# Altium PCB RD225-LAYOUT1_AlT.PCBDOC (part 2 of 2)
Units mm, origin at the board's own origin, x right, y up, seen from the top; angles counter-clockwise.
Board outline 85.6 x 53.98 mm, 2 copper layers (TOP, BOTTOM), stack 0 mm thick; 16 components, 11 nets, 48 pads, 0 vias.
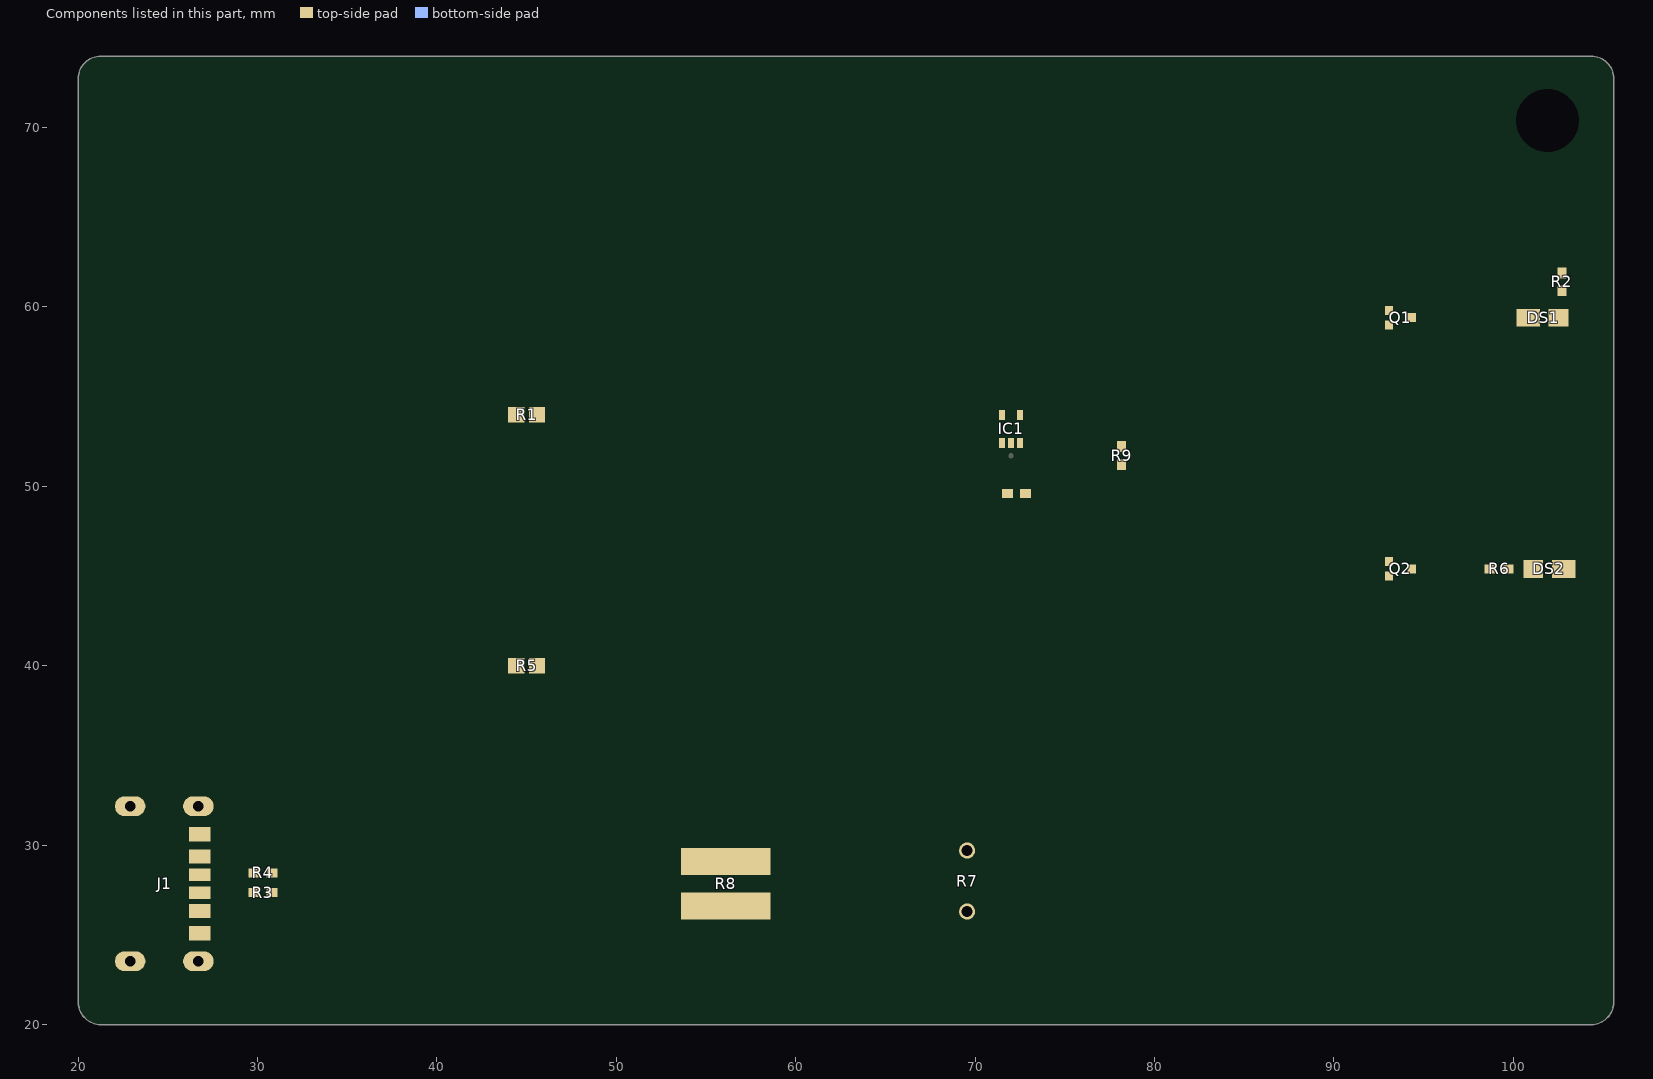
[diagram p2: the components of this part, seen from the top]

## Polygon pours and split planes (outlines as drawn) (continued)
no net on Top Overlay "TOPOVERLAY89" (solid, pour order 0): 25 vertices, not listed, extent 97.533,38.49 99.363,39.797
no net on Top Overlay "TOPOVERLAY88" (solid, pour order 0): 89.168,36.661 89.168,36.922 88.907,36.922 88.907,37.183 89.43,37.183 89.43,36.922 89.691,36.922 89.691,36.661
no net on Top Overlay "TOPOVERLAY87" (solid, pour order 0): 23 vertices, not listed, extent 96.226,34.308 98.056,36.138
no net on Top Overlay "TOPOVERLAY86" (solid, pour order 0): 100.932,35.354 100.932,35.615 101.193,35.615 101.193,35.354
no net on Top Overlay "TOPOVERLAY85" (solid, pour order 0): 99.625,34.569 99.625,34.831 99.886,34.831 99.886,34.569
no net on Top Overlay "TOPOVERLAY84" (solid, pour order 0): 101.193,33.785 101.193,34.046 101.454,34.046 101.454,33.785
no net on Top Overlay "TOPOVERLAY83" (solid, pour order 0): 93.089,30.387 93.089,30.648 93.351,30.648 93.351,31.694 93.612,31.694 93.612,31.432 93.874,31.432 93.874,31.694 94.135,31.694 94.135,31.171 94.396,31.171 94.396,30.91 93.612,30.91 93.612,30.387
no net on Top Overlay "TOPOVERLAY82" (solid, pour order 0): 88.646,39.275 88.646,41.104 90.475,41.104 90.475,39.275
no net on Top Overlay "TOPOVERLAY81" (solid, pour order 0): 97.272,39.013 97.272,39.275 97.533,39.275 97.533,39.013
no net on Top Overlay "TOPOVERLAY80" (solid, pour order 0): 94.919,34.569 94.919,34.831 95.181,34.831 95.181,34.569
no net on Top Overlay "TOPOVERLAY79" (solid, pour order 0): 89.691,37.968 89.691,38.752 89.953,38.752 89.953,38.49 90.737,38.49 90.737,38.229 89.953,38.229 89.953,37.968
no net on Top Overlay "TOPOVERLAY78" (solid, pour order 0): 96.488,29.603 96.488,29.864 96.749,29.864 96.749,29.603
no net on Top Overlay "TOPOVERLAY77" (solid, pour order 0): 100.409,32.739 100.409,33.001 100.67,33.001 100.67,32.739
no net on Top Overlay "TOPOVERLAY76" (solid, pour order 0): 100.147,33.001 100.147,33.262 100.409,33.262 100.409,33.001
no net on Top Overlay "TOPOVERLAY75" (solid, pour order 0): 89.691,32.739 89.691,33.001 89.953,33.001 89.953,33.262 90.475,33.262 90.475,33.001 90.214,33.001 90.214,32.739
no net on Top Overlay "TOPOVERLAY74" (solid, pour order 0): 92.044,31.432 92.044,31.694 91.521,31.694 91.521,31.955 91.782,31.955 91.782,32.217 92.044,32.217 92.044,31.955 92.305,31.955 92.305,31.432
no net on Top Overlay "TOPOVERLAY73" (solid, pour order 0): 33 vertices, not listed, extent 99.102,33.785 101.454,37.183
no net on Top Overlay "TOPOVERLAY72" (solid, pour order 0): 100.67,37.183 100.67,37.445 101.193,37.445 101.193,37.183
no net on Top Overlay "TOPOVERLAY71" (solid, pour order 0): 99.625,36.661 99.625,37.445 99.886,37.445 99.886,36.922 100.147,36.922 100.147,37.183 100.409,37.183 100.409,36.661
no net on Top Overlay "TOPOVERLAY70" (solid, pour order 0): 90.475,33.262 90.475,33.524 90.214,33.524 90.214,33.785 90.737,33.785 90.737,33.262
no net on Top Overlay "TOPOVERLAY69" (solid, pour order 0): 97.011,28.557 97.011,28.818 97.533,28.818 97.533,28.557
no net on Top Overlay "TOPOVERLAY68" (solid, pour order 0): 93.612,29.603 93.612,29.864 93.351,29.864 93.351,30.125 93.612,30.125 93.612,30.387 93.874,30.387 93.874,29.603
no net on Top Overlay "TOPOVERLAY67" (solid, pour order 0): 92.044,30.387 92.044,30.648 92.305,30.648 92.305,30.387
no net on Top Overlay "TOPOVERLAY66" (solid, pour order 0): 99.363,31.432 99.363,31.694 99.625,31.694 99.625,31.432
no net on Top Overlay "TOPOVERLAY65" (solid, pour order 0): 88.646,30.387 88.646,30.648 88.907,30.648 88.907,31.171 89.168,31.171 89.168,30.91 89.691,30.91 89.691,30.648 89.43,30.648 89.43,30.387
no net on Top Overlay "TOPOVERLAY64" (solid, pour order 0): 96.749,39.797 96.749,40.32 97.011,40.32 97.011,39.797
no net on Top Overlay "TOPOVERLAY63" (solid, pour order 0): 94.658,28.296 94.658,28.557 94.396,28.557 94.396,28.818 95.181,28.818 95.181,28.296
no net on Top Overlay "TOPOVERLAY62" (solid, pour order 0): 98.056,32.739 98.056,33.524 98.579,33.524 98.579,33.262 98.318,33.262 98.318,32.739
no net on Top Overlay "TOPOVERLAY61" (solid, pour order 0): 97.795,30.648 97.795,30.91 98.056,30.91 98.056,30.648
no net on Top Overlay "TOPOVERLAY60" (solid, pour order 0): 91.521,30.648 91.521,30.91 91.782,30.91 91.782,30.648
no net on Top Overlay "TOPOVERLAY59" (solid, pour order 0): 89.168,32.217 89.168,32.478 89.43,32.478 89.43,32.217
no net on Top Overlay "TOPOVERLAY58" (solid, pour order 0): 88.646,33.001 88.646,33.785 89.168,33.785 89.168,33.524 88.907,33.524 88.907,33.001
no net on Top Overlay "TOPOVERLAY57" (solid, pour order 0): 43 vertices, not listed, extent 89.168,33.001 92.305,35.615
no net on Top Overlay "TOPOVERLAY56" (solid, pour order 0): 90.998,37.183 90.998,37.706 91.521,37.706 91.521,37.445 91.26,37.445 91.26,37.183
no net on Top Overlay "TOPOVERLAY55" (solid, pour order 0): 96.226,29.864 96.226,30.387 96.488,30.387 96.488,29.864
no net on Top Overlay "TOPOVERLAY54" (solid, pour order 0): 89.168,35.615 89.168,35.876 89.43,35.876 89.43,35.615
no net on Top Overlay "TOPOVERLAY53" (solid, pour order 0): 89.953,38.752 89.953,39.013 90.737,39.013 90.737,38.752
no net on Top Overlay "TOPOVERLAY52" (solid, pour order 0): 90.737,39.013 90.737,39.536 90.998,39.536 90.998,39.013
no net on Top Overlay "TOPOVERLAY51" (solid, pour order 0): 91.26,31.432 91.26,31.694 91.521,31.694 91.521,31.432
no net on Top Overlay "TOPOVERLAY50" (solid, pour order 0): 45 vertices, not listed, extent 90.214,28.296 92.305,31.694
no net on Top Overlay "TOPOVERLAY49" (solid, pour order 0): 89.168,28.818 89.168,29.603 89.953,29.603 89.953,28.818
no net on Top Overlay "TOPOVERLAY48" (solid, pour order 0): 95.965,32.478 95.965,33.001 96.488,33.001 96.488,32.739 96.226,32.739 96.226,32.478
no net on Top Overlay "TOPOVERLAY47" (solid, pour order 0): 88.646,32.478 88.646,32.739 88.907,32.739 88.907,32.478
no net on Top Overlay "TOPOVERLAY46" (solid, pour order 0): 93.351,34.569 93.351,34.831 93.612,34.831 93.612,34.569
no net on Top Overlay "TOPOVERLAY45" (solid, pour order 0): 100.409,30.91 100.409,31.171 99.625,31.171 99.625,31.432 100.147,31.432 100.147,31.694 100.409,31.694 100.409,31.955 101.193,31.955 101.193,31.694 101.454,31.694 101.454,31.171 101.193,31.171 101.193,30.91
no net on Top Overlay "TOPOVERLAY44" (solid, pour order 0): 90.214,37.183 90.214,37.445 90.475,37.445 90.475,37.706 90.214,37.706 90.214,37.968 90.998,37.968 90.998,37.706 90.737,37.706 90.737,37.183
no net on Top Overlay "TOPOVERLAY43" (solid, pour order 0): 89.953,37.445 89.953,37.706 90.214,37.706 90.214,37.445
no net on Top Overlay "TOPOVERLAY42" (solid, pour order 0): 93.874,37.445 93.874,37.706 94.135,37.706 94.135,37.445
no net on Top Overlay "TOPOVERLAY41" (solid, pour order 0): 93.612,37.706 93.612,37.968 93.874,37.968 93.874,37.706
no net on Top Overlay "TOPOVERLAY40" (solid, pour order 0): 39 vertices, not listed, extent 97.011,39.275 99.363,41.104
no net on Top Overlay "TOPOVERLAY39" (solid, pour order 0): 92.044,30.91 92.044,31.171 92.305,31.171 92.305,30.91
no net on Top Overlay "TOPOVERLAY38" (solid, pour order 0): 19 vertices, not listed, extent 92.305,28.296 94.135,29.08
no net on Top Overlay "TOPOVERLAY37" (solid, pour order 0): 92.305,29.341 92.305,29.864 92.567,29.864 92.567,29.341
no net on Top Overlay "TOPOVERLAY36" (solid, pour order 0): 94.658,32.217 94.658,32.739 94.919,32.739 94.919,33.262 95.442,33.262 95.442,33.001 95.181,33.001 95.181,32.739 95.442,32.739 95.442,32.478 95.181,32.478 95.181,32.217
no net on Top Overlay "TOPOVERLAY35" (solid, pour order 0): 99.625,39.275 99.625,41.104 101.454,41.104 101.454,39.275
no net on Top Overlay "TOPOVERLAY34" (solid, pour order 0): 19 vertices, not listed, extent 92.305,29.08 93.351,30.648
no net on Top Overlay "TOPOVERLAY33" (solid, pour order 0): 94.135,36.661 94.135,37.445 94.658,37.445 94.658,37.183 94.396,37.183 94.396,36.661
no net on Top Overlay "TOPOVERLAY32" (solid, pour order 0): 41 vertices, not listed, extent 96.749,28.296 98.579,30.91
no net on Top Overlay "TOPOVERLAY31" (solid, pour order 0): 95.181,31.432 95.181,32.217 95.965,32.217 95.965,31.955 95.704,31.955 95.704,31.694 95.442,31.694 95.442,31.432
no net on Top Overlay "TOPOVERLAY30" (solid, pour order 0): 39 vertices, not listed, extent 94.135,28.818 97.011,31.171
no net on Top Overlay "TOPOVERLAY29" (solid, pour order 0): 92.828,31.432 92.828,31.694 93.089,31.694 93.089,31.432
no net on Top Overlay "TOPOVERLAY28" (solid, pour order 0): 100.932,38.49 100.932,39.013 101.454,39.013 101.454,38.752 101.193,38.752 101.193,38.49
no net on Top Overlay "TOPOVERLAY27" (solid, pour order 0): 25 vertices, not listed, extent 98.579,31.694 100.409,33.785
no net on Top Overlay "TOPOVERLAY26" (solid, pour order 0): 98.318,33.785 98.318,34.046 98.579,34.046 98.579,34.308 97.795,34.308 97.795,34.569 98.056,34.569 98.056,35.092 98.579,35.092 98.579,34.831 98.84,34.831 98.84,33.785
no net on Top Overlay "TOPOVERLAY25" (solid, pour order 0): 94.842,22.923 94.842,25.028 95.435,25.028 95.435,24.26 96.124,24.26 96.124,25.028 96.717,25.028 96.717,22.923 96.124,22.923 96.124,23.733 95.435,23.733 95.435,22.923
no net on Top Overlay "TOPOVERLAY24" (solid, pour order 0): 88.822,22.923 88.822,22.929 88.816,22.929 88.816,24.502 88.193,24.502 88.193,25.028 90.075,25.028 90.075,25.022 90.081,25.022 90.081,24.502 89.451,24.502 89.451,22.923
no net on Top Overlay "TOPOVERLAY23" (solid, pour order 0): 501 vertices, not listed, extent 100.335,22.923 102.483,25.028
no net on Top Overlay "TOPOVERLAY22" (solid, pour order 0): 873 vertices, not listed, extent 92.615,22.886 94.449,25.064
no net on Top Overlay "TOPOVERLAY21" (solid, pour order 0): 19 vertices, not listed, extent 96.749,32.739 97.795,34.569
no net on Top Overlay "TOPOVERLAY20" (solid, pour order 0): 98.84,28.296 98.84,29.08 99.102,29.08 99.102,28.818 99.625,28.818 99.625,28.296
no net on Top Overlay "TOPOVERLAY19" (solid, pour order 0): 33 vertices, not listed, extent 89.43,30.91 91.521,33.262
no net on Top Overlay "TOPOVERLAY18" (solid, pour order 0): 92.828,34.569 92.828,34.831 93.089,34.831 93.089,34.569
no net on Top Overlay "TOPOVERLAY17" (solid, pour order 0): 171 vertices, not listed, extent 91.26,34.569 98.318,41.104
no net on Top Overlay "TOPOVERLAY16" (solid, pour order 0): 49 vertices, not listed, extent 98.056,35.615 101.454,39.013
no net on Top Overlay "TOPOVERLAY15" (solid, pour order 0): 517 vertices, not listed, extent 90.274,22.886 92.271,25.064
no net on Top Overlay "TOPOVERLAY14" (solid, pour order 0): 363 vertices, not listed, extent 98.363,22.923 100.184,25.028
no net on Top Overlay "TOPOVERLAY13" (solid, pour order 0): 97.237,22.923 97.237,25.028 97.836,25.028 97.836,22.923
no net on Top Overlay "TOPOVERLAY12" (solid, pour order 0): 92.828,30.648 92.828,30.91 92.567,30.91 92.567,31.171 93.089,31.171 93.089,30.648
no net on Top Overlay "TOPOVERLAY11" (solid, pour order 0): 98.318,35.354 98.318,35.615 98.579,35.615 98.579,35.354
no net on Top Overlay "TOPOVERLAY10" (solid, pour order 0): 95 vertices, not listed, extent 91.782,32.217 96.749,36.661
no net on Top Overlay "TOPOVERLAY9" (solid, pour order 0): 43 vertices, not listed, extent 98.579,28.296 101.454,30.91
no net on Top Overlay "TOPOVERLAY8" (solid, pour order 0): 98.579,30.387 98.579,30.648 98.84,30.648 98.84,30.387
no net on Top Overlay "TOPOVERLAY7" (solid, pour order 0): 27 vertices, not listed, extent 97.011,30.648 99.363,32.478
no net on Top Overlay "TOPOVERLAY6" (solid, pour order 0): 90.475,35.876 90.475,36.138 90.737,36.138 90.737,36.661 89.953,36.661 89.953,36.922 90.998,36.922 90.998,36.661 91.26,36.661 91.26,36.399 90.998,36.399 90.998,35.876
no net on Top Overlay "TOPOVERLAY5" (solid, pour order 0): 88.907,37.445 88.907,37.706 88.646,37.706 88.646,38.49 88.907,38.49 88.907,37.968 89.168,37.968 89.168,39.013 89.691,39.013 89.691,38.752 89.43,38.752 89.43,37.445
no net on Top Overlay "TOPOVERLAY4" (solid, pour order 0): 100.67,30.387 100.67,30.648 100.932,30.648 100.932,30.387

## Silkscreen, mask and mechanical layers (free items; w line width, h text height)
Top Overlay:
  drawing of 1029 lines, arcs and shapes, not listed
